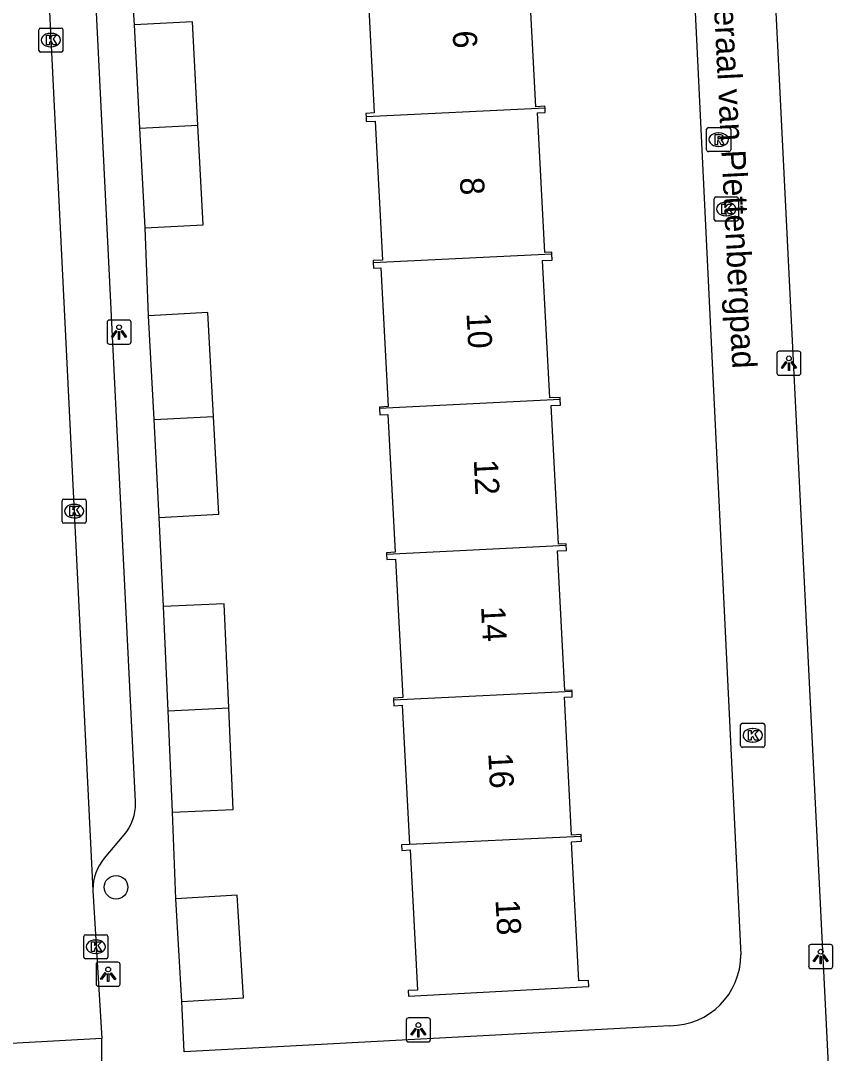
# Model space of a CAD drawing. Extents: x 161084 to 161928, y 385355 to 386522.
# Drawn here: x 161328.54 to 161362.7, y 385671.84 to 385714.61 of the extents above; entities that cross this region are included whole.
import ezdxf

# ---------------------------------------------------------------- set-up
doc = ezdxf.new("R2010")
doc.units = 0
for name, color, linetype in [('IMGEO_Boom', 7, 'Continuous'), ('IMGEO_Kolk', 7, 'Continuous'), ('IMGEO_Lichtpunt', 7, 'Continuous'), ('IMGEO_Openbare_ruimte_label', 7, 'Continuous'), ('IMGEO_Pand', 7, 'Continuous'), ('IMGEO_Pand_nummerreeks', 7, 'Continuous'), ('IMGEO_Rijbaan_lokaal_open', 7, 'Continuous'), ('IMGEO_Rioolput', 7, 'Continuous'), ('IMGEO_Voetpad_open', 7, 'Continuous')]:
    doc.layers.add(name, color=color, linetype=linetype)

msp = doc.modelspace()

# ---------------------------------------------------------------- linework, layer by layer
at = {"layer": 'IMGEO_Boom'}
msp.add_circle((161332.487, 385678.721), 0.489, dxfattribs=at)
at = {"layer": 'IMGEO_Kolk'}
for p, q in [((161329.288, 385713.382), (161329.288, 385714.234)), ((161329.363, 385714.308), (161330.215, 385714.308)), ((161329.776, 385714.088), (161329.801, 385714.088)), ((161330.289, 385714.234), (161330.289, 385713.382)), ((161330.215, 385713.308), (161329.363, 385713.308)), ((161329.799, 385713.528), (161329.774, 385713.528)), ((161357.263, 385706.384), (161357.263, 385707.236)), ((161357.338, 385707.31), (161358.19, 385707.31)), ((161358.264, 385707.236), (161358.264, 385706.384)), ((161357.751, 385707.09), (161357.776, 385707.09)), ((161358.19, 385706.31), (161357.338, 385706.31)), ((161357.774, 385706.53), (161357.749, 385706.53)), ((161330.326, 385694.798), (161331.178, 385694.798)), ((161330.251, 385693.872), (161330.251, 385694.724)), ((161330.739, 385694.578), (161330.764, 385694.578)), ((161331.252, 385694.724), (161331.252, 385693.872)), ((161330.762, 385694.018), (161330.737, 385694.018)), ((161331.178, 385693.798), (161330.326, 385693.798)), ((161358.357, 385684.59), (161358.357, 385685.442)), ((161358.432, 385685.516), (161359.284, 385685.516)), ((161359.358, 385685.442), (161359.358, 385684.59)), ((161358.845, 385685.296), (161358.87, 385685.296)), ((161359.284, 385684.516), (161358.432, 385684.516)), ((161358.868, 385684.736), (161358.843, 385684.736)), ((161331.147, 385675.83), (161331.147, 385676.682)), ((161331.222, 385676.756), (161332.074, 385676.756)), ((161331.635, 385676.536), (161331.66, 385676.536)), ((161332.148, 385676.682), (161332.148, 385675.83)), ((161331.658, 385675.976), (161331.633, 385675.976)), ((161332.074, 385675.756), (161331.222, 385675.756))]:
    msp.add_line(p, q, dxfattribs=at)
for points in [[(161329.288, 385713.382), (161329.288, 385714.234)], [(161329.363, 385714.308), (161330.215, 385714.308)], [(161329.609, 385714.008), (161329.732, 385714.008), (161329.732, 385713.857), (161329.862, 385714.008), (161330.026, 385714.008), (161329.88, 385713.857), (161330.033, 385713.608), (161329.881, 385713.608), (161329.796, 385713.772), (161329.732, 385713.705), (161329.732, 385713.608), (161329.609, 385713.608), (161329.609, 385714.008)], [(161330.289, 385714.234), (161330.289, 385713.382)], [(161330.215, 385713.308), (161329.363, 385713.308)], [(161357.263, 385706.384), (161357.263, 385707.236)], [(161357.338, 385707.31), (161358.19, 385707.31)], [(161358.264, 385707.236), (161358.264, 385706.384)], [(161357.584, 385707.01), (161357.707, 385707.01), (161357.707, 385706.859), (161357.837, 385707.01), (161358.001, 385707.01), (161357.855, 385706.859), (161358.008, 385706.61), (161357.856, 385706.61), (161357.771, 385706.774), (161357.707, 385706.707), (161357.707, 385706.61), (161357.584, 385706.61), (161357.584, 385707.01)], [(161358.19, 385706.31), (161357.338, 385706.31)], [(161330.326, 385694.798), (161331.178, 385694.798)], [(161330.251, 385693.872), (161330.251, 385694.724)], [(161330.572, 385694.498), (161330.695, 385694.498), (161330.695, 385694.347), (161330.825, 385694.498), (161330.989, 385694.498), (161330.843, 385694.347), (161330.996, 385694.098), (161330.844, 385694.098), (161330.759, 385694.262), (161330.695, 385694.195), (161330.695, 385694.098), (161330.572, 385694.098), (161330.572, 385694.498)], [(161331.252, 385694.724), (161331.252, 385693.872)], [(161331.178, 385693.798), (161330.326, 385693.798)], [(161358.357, 385684.59), (161358.357, 385685.442)], [(161358.432, 385685.516), (161359.284, 385685.516)], [(161359.358, 385685.442), (161359.358, 385684.59)], [(161358.678, 385685.216), (161358.801, 385685.216), (161358.801, 385685.065), (161358.931, 385685.216), (161359.095, 385685.216), (161358.949, 385685.065), (161359.102, 385684.816), (161358.95, 385684.816), (161358.865, 385684.98), (161358.801, 385684.913), (161358.801, 385684.816), (161358.678, 385684.816), (161358.678, 385685.216)], [(161359.284, 385684.516), (161358.432, 385684.516)], [(161331.147, 385675.83), (161331.147, 385676.682)], [(161331.222, 385676.756), (161332.074, 385676.756)], [(161331.468, 385676.456), (161331.591, 385676.456), (161331.591, 385676.305), (161331.721, 385676.456), (161331.885, 385676.456), (161331.739, 385676.305), (161331.892, 385676.056), (161331.74, 385676.056), (161331.655, 385676.22), (161331.591, 385676.153), (161331.591, 385676.056), (161331.468, 385676.056), (161331.468, 385676.456)], [(161332.148, 385676.682), (161332.148, 385675.83)], [(161332.074, 385675.756), (161331.222, 385675.756)]]:
    msp.add_lwpolyline(points, dxfattribs=at)
for centre, start, end in [((161329.365, 385714.232), 91.552, 178.448), ((161329.365, 385714.232), 91.552, 178.448), ((161330.213, 385714.232), 1.552, 88.448), ((161330.213, 385714.232), 1.552, 88.448), ((161329.365, 385713.384), 181.552, 268.448), ((161329.365, 385713.384), 181.552, 268.448), ((161330.213, 385713.384), 271.552, 358.448), ((161330.213, 385713.384), 271.552, 358.448), ((161357.34, 385707.234), 91.552, 178.448), ((161357.34, 385707.234), 91.552, 178.448), ((161358.188, 385707.234), 1.552, 88.448), ((161358.188, 385707.234), 1.552, 88.448), ((161357.34, 385706.386), 181.552, 268.448), ((161357.34, 385706.386), 181.552, 268.448), ((161358.188, 385706.386), 271.552, 358.448), ((161358.188, 385706.386), 271.552, 358.448), ((161330.328, 385694.722), 91.552, 178.448), ((161330.328, 385694.722), 91.552, 178.448), ((161331.176, 385694.722), 1.552, 88.448), ((161331.176, 385694.722), 1.552, 88.448), ((161330.328, 385693.874), 181.552, 268.448), ((161330.328, 385693.874), 181.552, 268.448), ((161331.176, 385693.874), 271.552, 358.448), ((161331.176, 385693.874), 271.552, 358.448), ((161358.434, 385685.44), 91.552, 178.448), ((161358.434, 385685.44), 91.552, 178.448), ((161359.282, 385685.44), 1.552, 88.448), ((161359.282, 385685.44), 1.552, 88.448), ((161358.434, 385684.592), 181.552, 268.448), ((161358.434, 385684.592), 181.552, 268.448), ((161359.282, 385684.592), 271.552, 358.448), ((161359.282, 385684.592), 271.552, 358.448), ((161331.224, 385676.68), 91.552, 178.448), ((161331.224, 385676.68), 91.552, 178.448), ((161332.072, 385676.68), 1.552, 88.448), ((161332.072, 385676.68), 1.552, 88.448), ((161331.224, 385675.832), 181.552, 268.448), ((161331.224, 385675.832), 181.552, 268.448), ((161332.072, 385675.832), 271.552, 358.448), ((161332.072, 385675.832), 271.552, 358.448)]:
    msp.add_arc(centre, 0.0765, start, end, dxfattribs=at)
for centre, major_axis, ratio, start_param, end_param in [((161329.775, 385713.808), (-0.387, 0.002), 0.722429, 4.712389, 7.853982), ((161329.8, 385713.808), (-0.39, 0.002), 0.717154, 1.570796, 4.712389), ((161357.75, 385706.81), (-0.387, 0.002), 0.722429, 4.712389, 7.853982), ((161357.775, 385706.81), (-0.39, 0.002), 0.717154, 1.570796, 4.712389), ((161330.738, 385694.298), (-0.387, 0.002), 0.722429, 4.712389, 7.853982), ((161330.763, 385694.298), (-0.39, 0.002), 0.717154, 1.570796, 4.712389), ((161358.844, 385685.016), (-0.387, 0.002), 0.722429, 4.712389, 7.853982), ((161358.869, 385685.016), (-0.39, 0.002), 0.717154, 1.570796, 4.712389), ((161331.634, 385676.256), (-0.387, 0.002), 0.722429, 4.712389, 7.853982), ((161331.659, 385676.256), (-0.39, 0.002), 0.717154, 1.570796, 4.712389)]:
    msp.add_ellipse(centre, major_axis=major_axis, ratio=ratio, start_param=start_param, end_param=end_param, dxfattribs=at)
at = {"layer": 'IMGEO_Lichtpunt'}
for p, q in [((161332.113, 385702.116), (161332.113, 385701.309)), ((161332.113, 385702.116), (161332.113, 385701.309)), ((161333.015, 385702.211), (161332.207, 385702.211)), ((161333.015, 385702.211), (161332.207, 385702.211)), ((161333.109, 385701.309), (161333.109, 385702.116)), ((161333.109, 385701.309), (161333.109, 385702.116)), ((161332.207, 385701.215), (161333.015, 385701.215)), ((161332.207, 385701.215), (161333.015, 385701.215)), ((161359.86, 385700.827), (161359.86, 385700.02)), ((161359.86, 385700.827), (161359.86, 385700.02)), ((161360.762, 385700.922), (161359.954, 385700.922)), ((161360.762, 385700.922), (161359.954, 385700.922)), ((161360.856, 385700.02), (161360.856, 385700.827)), ((161360.856, 385700.02), (161360.856, 385700.827)), ((161359.954, 385699.926), (161360.762, 385699.926)), ((161359.954, 385699.926), (161360.762, 385699.926)), ((161361.177, 385676.253), (161361.177, 385675.446)), ((161361.177, 385676.253), (161361.177, 385675.446)), ((161362.079, 385676.348), (161361.271, 385676.348)), ((161362.079, 385676.348), (161361.271, 385676.348)), ((161362.173, 385675.446), (161362.173, 385676.253)), ((161362.173, 385675.446), (161362.173, 385676.253)), ((161331.66, 385675.519), (161331.66, 385674.712)), ((161331.66, 385675.519), (161331.66, 385674.712)), ((161332.562, 385675.614), (161331.754, 385675.614)), ((161332.562, 385675.614), (161331.754, 385675.614)), ((161332.656, 385674.712), (161332.656, 385675.519)), ((161332.656, 385674.712), (161332.656, 385675.519)), ((161361.271, 385675.352), (161362.079, 385675.352)), ((161361.271, 385675.352), (161362.079, 385675.352)), ((161331.754, 385674.618), (161332.562, 385674.618)), ((161331.754, 385674.618), (161332.562, 385674.618)), ((161344.511, 385673.215), (161344.511, 385672.408)), ((161344.511, 385673.215), (161344.511, 385672.408)), ((161345.413, 385673.31), (161344.605, 385673.31)), ((161345.413, 385673.31), (161344.605, 385673.31)), ((161345.507, 385672.408), (161345.507, 385673.215)), ((161345.507, 385672.408), (161345.507, 385673.215)), ((161344.605, 385672.314), (161345.413, 385672.314)), ((161344.605, 385672.314), (161345.413, 385672.314))]:
    msp.add_line(p, q, dxfattribs=at)
for points in [[(161332.487, 385701.78), (161332.526, 385701.752), (161332.338, 385701.49), (161332.3, 385701.517), (161332.487, 385701.78)], [(161332.589, 385701.732), (161332.636, 385701.732), (161332.636, 385701.41), (161332.589, 385701.41), (161332.589, 385701.732)], [(161332.699, 385701.752), (161332.737, 385701.779), (161332.924, 385701.517), (161332.885, 385701.489), (161332.699, 385701.752)], [(161360.234, 385700.491), (161360.273, 385700.463), (161360.085, 385700.201), (161360.047, 385700.228), (161360.234, 385700.491)], [(161360.336, 385700.443), (161360.383, 385700.443), (161360.383, 385700.121), (161360.336, 385700.121), (161360.336, 385700.443)], [(161360.446, 385700.463), (161360.484, 385700.49), (161360.671, 385700.228), (161360.632, 385700.2), (161360.446, 385700.463)], [(161361.551, 385675.917), (161361.59, 385675.889), (161361.402, 385675.627), (161361.364, 385675.654), (161361.551, 385675.917)], [(161361.653, 385675.869), (161361.7, 385675.869), (161361.7, 385675.547), (161361.653, 385675.547), (161361.653, 385675.869)], [(161361.763, 385675.889), (161361.801, 385675.916), (161361.988, 385675.654), (161361.949, 385675.626), (161361.763, 385675.889)], [(161332.034, 385675.183), (161332.073, 385675.155), (161331.885, 385674.893), (161331.847, 385674.92), (161332.034, 385675.183)], [(161332.136, 385675.135), (161332.183, 385675.135), (161332.183, 385674.813), (161332.136, 385674.813), (161332.136, 385675.135)], [(161332.246, 385675.155), (161332.284, 385675.182), (161332.471, 385674.92), (161332.432, 385674.892), (161332.246, 385675.155)], [(161344.885, 385672.879), (161344.924, 385672.851), (161344.736, 385672.589), (161344.698, 385672.616), (161344.885, 385672.879)], [(161344.987, 385672.831), (161345.034, 385672.831), (161345.034, 385672.509), (161344.987, 385672.509), (161344.987, 385672.831)], [(161345.097, 385672.851), (161345.135, 385672.878), (161345.322, 385672.616), (161345.283, 385672.588), (161345.097, 385672.851)]]:
    msp.add_lwpolyline(points, dxfattribs=at)
for centre in [(161332.612, 385701.914), (161360.359, 385700.625), (161361.676, 385676.051), (161332.159, 385675.317), (161345.01, 385673.013)]:
    msp.add_circle(centre, 0.0994, dxfattribs=at)
for centre, start, end in [((161332.207, 385702.116), 90, 180), ((161332.207, 385702.116), 90, 180), ((161333.015, 385702.116), 0, 90), ((161333.015, 385702.116), 0, 90), ((161332.207, 385701.309), 180, 270), ((161332.207, 385701.309), 180, 270), ((161333.015, 385701.309), 270, 0), ((161333.015, 385701.309), 270, 360), ((161359.954, 385700.827), 90, 180), ((161359.954, 385700.827), 90, 180), ((161360.762, 385700.827), 0, 90), ((161360.762, 385700.827), 0, 90), ((161359.954, 385700.02), 180, 270), ((161359.954, 385700.02), 180, 270), ((161360.762, 385700.02), 270, 0), ((161360.762, 385700.02), 270, 360), ((161361.271, 385676.253), 90, 180), ((161361.271, 385676.253), 90, 180), ((161362.079, 385676.253), 0, 90), ((161362.079, 385676.253), 0, 90), ((161331.754, 385675.519), 90, 180), ((161331.754, 385675.519), 90, 180), ((161332.562, 385675.519), 0, 90), ((161332.562, 385675.519), 0, 90), ((161361.271, 385675.446), 180, 270), ((161361.271, 385675.446), 180, 270), ((161362.079, 385675.446), 270, 0), ((161362.079, 385675.446), 270, 360), ((161331.754, 385674.712), 180, 270), ((161331.754, 385674.712), 180, 270), ((161332.562, 385674.712), 270, 0), ((161332.562, 385674.712), 270, 360), ((161344.605, 385673.215), 90, 180), ((161344.605, 385673.215), 90, 180), ((161345.413, 385673.215), 0, 90), ((161345.413, 385673.215), 0, 90), ((161344.605, 385672.408), 180, 270), ((161344.605, 385672.408), 180, 270), ((161345.413, 385672.408), 270, 0), ((161345.413, 385672.408), 270, 360)]:
    msp.add_arc(centre, 0.0946, start, end, dxfattribs=at)
at = {"layer": 'IMGEO_Pand'}
for points in [[(161350.256, 385710.994), (161350.252, 385711.066), (161349.881, 385711.046), (161349.576, 385716.816), (161349.96, 385716.836), (161349.95, 385717.029)], [(161342.538, 385716.663), (161342.549, 385716.453), (161342.884, 385716.47), (161343.184, 385710.792), (161342.836, 385710.774), (161342.842, 385710.628)], [(161335.88, 385710.284), (161335.657, 385714.566), (161333.255, 385714.441)], [(161333.478, 385710.166), (161333.255, 385714.441)], [(161350.256, 385710.994), (161342.842, 385710.628)], [(161342.842, 385710.628), (161342.85, 385710.438), (161343.214, 385710.453), (161343.52, 385704.699), (161343.133, 385704.679), (161343.138, 385704.592)], [(161350.535, 385704.957), (161350.532, 385705.022), (161350.245, 385705.007), (161349.939, 385710.795), (161350.266, 385710.812), (161350.256, 385710.994)], [(161333.478, 385710.166), (161335.88, 385710.284)], [(161333.693, 385706.027), (161333.478, 385710.166)], [(161333.693, 385706.027), (161336.095, 385706.152), (161335.88, 385710.284)], [(161343.138, 385704.592), (161350.535, 385704.957)], [(161343.138, 385704.592), (161343.15, 385704.362), (161343.458, 385704.378), (161343.762, 385698.63), (161343.402, 385698.61), (161343.405, 385698.555)], [(161350.882, 385698.925), (161350.877, 385699.009), (161350.456, 385698.986), (161350.155, 385704.673), (161350.549, 385704.694), (161350.535, 385704.957)], [(161336.521, 385698.214), (161336.289, 385702.524), (161333.83, 385702.392)], [(161334.061, 385698.093), (161333.83, 385702.392)], [(161350.882, 385698.925), (161343.405, 385698.555)], [(161351.131, 385692.886), (161351.128, 385692.943), (161350.821, 385692.927), (161350.517, 385698.67), (161350.895, 385698.69), (161350.882, 385698.925)], [(161334.061, 385698.093), (161336.521, 385698.214)], [(161334.279, 385694.038), (161336.738, 385694.17), (161336.521, 385698.214)], [(161343.405, 385698.555), (161343.42, 385698.281), (161343.747, 385698.298), (161344.049, 385692.594), (161343.686, 385692.575), (161343.689, 385692.519)], [(161334.279, 385694.038), (161334.061, 385698.093)], [(161343.689, 385692.519), (161351.131, 385692.886)], [(161351.374, 385686.847), (161351.372, 385686.881), (161351.072, 385686.866), (161350.766, 385692.651), (161351.142, 385692.671), (161351.131, 385692.886)], [(161343.689, 385692.519), (161343.701, 385692.295), (161344.059, 385692.314), (161344.363, 385686.576), (161343.978, 385686.555), (161343.982, 385686.483)], [(161337.156, 385686.147), (161336.964, 385690.459), (161334.451, 385690.347)], [(161334.643, 385686.023), (161334.451, 385690.347)], [(161343.982, 385686.483), (161351.374, 385686.847)], [(161351.754, 385680.817), (161351.75, 385680.899), (161351.358, 385680.878), (161351.056, 385686.593), (161351.386, 385686.61), (161351.374, 385686.847)], [(161343.982, 385686.483), (161343.995, 385686.241), (161344.335, 385686.259), (161344.64, 385680.496)], [(161334.643, 385686.023), (161337.156, 385686.147)], [(161334.83, 385681.831), (161334.643, 385686.023)], [(161334.83, 385681.831), (161337.343, 385681.943), (161337.156, 385686.147)], [(161344.64, 385680.496), (161344.306, 385680.478), (161344.318, 385680.247), (161344.666, 385680.265), (161344.973, 385674.461), (161344.589, 385674.441), (161344.601, 385674.215), (161352.064, 385674.61), (161352.051, 385674.863), (161351.654, 385674.842), (161351.348, 385680.604), (161351.764, 385680.626), (161351.754, 385680.817)], [(161351.754, 385680.817), (161344.64, 385680.496)], [(161335.218, 385673.99), (161337.763, 385674.142), (161337.509, 385678.394), (161334.964, 385678.242)], [(161335.218, 385673.99), (161334.964, 385678.242)]]:
    msp.add_lwpolyline(points, dxfattribs=at)
at = {"layer": 'IMGEO_Rijbaan_lokaal_open'}
for points in [[(161329.112, 385727.598), (161331.531, 385678.586)], [(161331.531, 385678.586), (161331.899, 385672.456)], [(161331.899, 385672.456), (161326.625, 385672.163)]]:
    msp.add_lwpolyline(points, dxfattribs=at)
at = {"layer": 'IMGEO_Rioolput'}
for p, q in [((161357.022, 385710.187), (161357.874, 385710.187)), ((161356.947, 385709.261), (161356.947, 385710.113)), ((161357.435, 385709.967), (161357.46, 385709.967)), ((161357.948, 385710.113), (161357.948, 385709.261)), ((161357.458, 385709.407), (161357.433, 385709.407)), ((161357.874, 385709.187), (161357.022, 385709.187))]:
    msp.add_line(p, q, dxfattribs=at)
for points in [[(161357.022, 385710.187), (161357.874, 385710.187)], [(161356.947, 385709.261), (161356.947, 385710.113)], [(161357.536, 385709.885), (161357.284, 385709.887), (161357.284, 385709.487)], [(161357.462, 385709.806), (161357.408, 385709.806), (161357.408, 385709.725)], [(161357.408, 385709.725), (161357.46, 385709.725)], [(161357.948, 385710.113), (161357.948, 385709.261)], [(161357.284, 385709.487), (161357.408, 385709.487), (161357.408, 385709.649), (161357.419, 385709.649)], [(161357.466, 385709.62), (161357.537, 385709.487), (161357.677, 385709.487), (161357.612, 385709.613)], [(161357.874, 385709.187), (161357.022, 385709.187)]]:
    msp.add_lwpolyline(points, dxfattribs=at)
for centre, radius, start, end in [((161357.024, 385710.111), 0.0765, 91.552, 178.448), ((161357.024, 385710.111), 0.0765, 91.552, 178.448), ((161357.872, 385710.111), 0.0765, 1.552, 88.448), ((161357.872, 385710.111), 0.0765, 1.552, 88.448), ((161357.444, 385709.914), 0.19, 274.7715, 282.9687), ((161357.468, 385709.71), 0.0964, 77.0061, 93.1865), ((161357.482, 385709.767), 0.0378, 276.6634, 79.6772), ((161357.535, 385709.775), 0.109, 350.3612, 89.416), ((161357.533, 385709.775), 0.112, 277.5842, 350.9817), ((161357.418, 385709.596), 0.0533, 26.0293, 88.6989), ((161357.517, 385709.56), 0.108, 29.5134, 73.7905), ((161357.024, 385709.263), 0.0765, 181.552, 268.448), ((161357.024, 385709.263), 0.0765, 181.552, 268.448), ((161357.872, 385709.263), 0.0765, 271.552, 358.448), ((161357.872, 385709.263), 0.0765, 271.552, 358.448)]:
    msp.add_arc(centre, radius, start, end, dxfattribs=at)
for centre, major_axis, ratio, start_param, end_param in [((161357.434, 385709.687), (-0.387, 0.002), 0.722429, 4.712389, 7.853982), ((161357.459, 385709.687), (-0.39, 0.002), 0.717154, 1.570796, 4.712389)]:
    msp.add_ellipse(centre, major_axis=major_axis, ratio=ratio, start_param=start_param, end_param=end_param, dxfattribs=at)
at = {"layer": 'IMGEO_Voetpad_open'}
for points in [[(161358.884, 385733.846), (161362.696, 385656.941)], [(161355.595, 385733.21), (161358.367, 385675.925)], [(161331.211, 385724.18), (161333.28, 385682.275), (161333.282, 385682.209), (161333.277, 385682.03), (161333.256, 385681.852), (161333.219, 385681.677), (161333.166, 385681.506), (161333.098, 385681.34), (161333.016, 385681.18), (161332.92, 385681.029), (161332.811, 385680.887), (161332, 385679.925), (161331.892, 385679.786), (161331.797, 385679.637), (161331.715, 385679.481), (161331.648, 385679.317), (161331.595, 385679.149), (161331.558, 385678.976), (161331.536, 385678.801), (161331.53, 385678.625), (161331.531, 385678.586)], [(161333.255, 385714.441), (161333.011, 385718.11)], [(161333.83, 385702.392), (161333.693, 385706.027)], [(161334.451, 385690.347), (161334.279, 385694.038)], [(161334.964, 385678.242), (161334.83, 385681.831)], [(161355.429, 385672.987), (161335.31, 385671.898), (161335.218, 385673.99)], [(161331.899, 385671.174), (161331.899, 385672.456)]]:
    msp.add_lwpolyline(points, dxfattribs=at)
msp.add_arc((161355.426, 385675.928), 2.941, 270.0609, 359.9391, dxfattribs=at)

# ---------------------------------------------------------------- texts
at = {"layer": 'IMGEO_Openbare_ruimte_label'}
msp.add_text('Generaal van Plettenbergpad', height=1, rotation=272.9225, dxfattribs=at).set_placement((161357.129, 385717.628))
at = {"layer": 'IMGEO_Pand_nummerreeks'}
for s, rotation, p in [('6', 272.8302, (161346.427, 385714.184)), ('8', 272.8302, (161346.727, 385708.106)), ('10', 272.8302, (161347.004, 385702.493)), ('12', 272.8302, (161347.304, 385696.425)), ('14', 272.8302, (161347.605, 385690.347)), ('16', 272.8302, (161347.905, 385684.273)), ('18', 272.8291, (161348.206, 385678.196))]:
    msp.add_text(s, height=1, rotation=rotation, dxfattribs=at).set_placement(p)

doc.saveas('drawing.dxf')
